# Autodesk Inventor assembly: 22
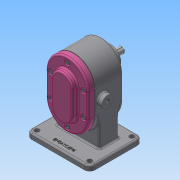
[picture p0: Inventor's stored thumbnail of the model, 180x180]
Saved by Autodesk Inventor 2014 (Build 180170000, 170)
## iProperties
Created: 2020-09
Part Number: 22
Document SubType Name: Assembly
Designer: net
Author: net
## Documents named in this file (11)
- C:\Users\net\Desktop\700906V1001\22.iam
- C:\Users\net\Desktop\700906V1001\Ű 6 x 6 x 18.ipt
- C:\Users\net\Desktop\700906V1001\개스킷.ipt
- C:\Users\net\Desktop\700906V1001\메인축.ipt
- C:\Users\net\Desktop\700906V1001\베어링부시.ipt
- C:\Users\net\Desktop\700906V1001\본체.ipt
- C:\Users\net\Desktop\700906V1001\볼트 M5.ipt
- C:\Users\net\Desktop\700906V1001\서브축.ipt
- C:\Users\net\Desktop\700906V1001\스퍼기어.ipt
- C:\Users\net\Desktop\700906V1001\오일 실 16 28 7.ipt
- C:\Users\net\Desktop\700906V1001\커버.ipt
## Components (3 placed, 2 different names)
1. Ű 6 x 6 x 18:1
2. 개스킷:1
3. Ű 6 x 6 x 18:2
